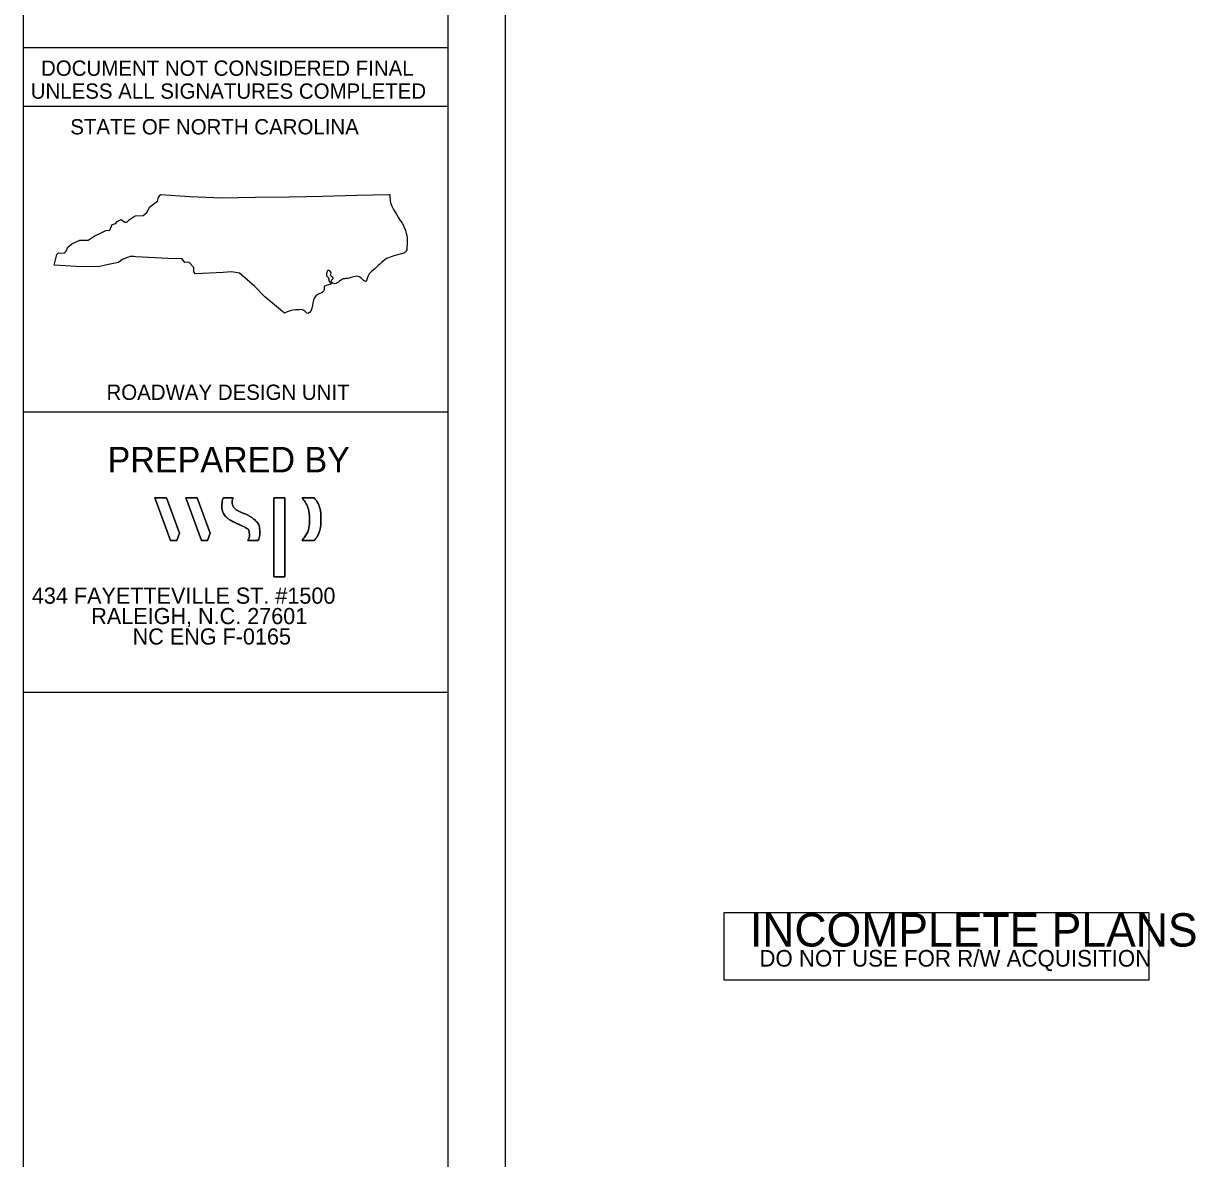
# Model space of a CAD drawing. Extents: x 1553884 to 1554215, y 810431 to 810779.
# Drawn here: x 1554139.32 to 1554180.72, y 810513.45 to 810553.55 of the extents above; entities that cross this region are included whole.
import ezdxf

# ---------------------------------------------------------------- set-up
doc = ezdxf.new("R2010")
doc.units = 0
for name, color, linetype in [('Old_Level_1', 7, 'Continuous'), ('Old_Level_11', 7, 'Continuous'), ('Old_Level_2', 7, 'Continuous'), ('Prop Lane Arrow CELL', 7, 'Continuous'), ('Sheet Professional Seal CELL', 7, 'Continuous'), ('Typical Arrow Superelevation CELL', 7, 'Continuous')]:
    doc.layers.add(name, color=color, linetype=linetype)

msp = doc.modelspace()

# ---------------------------------------------------------------- linework, layer by layer
at = {"layer": 'Old_Level_1'}
msp.add_line((1554152.261, 810547.506), (1554152.26, 810547.512), dxfattribs=at)
for points in [[(1554140.411, 810545.014), (1554140.505, 810545.385), (1554140.563, 810545.452), (1554140.763, 810545.439), (1554140.831, 810545.504), (1554140.884, 810545.649), (1554141.034, 810545.766), (1554141.313, 810545.893), (1554141.607, 810545.896), (1554141.815, 810546.042), (1554142.093, 810546.166), (1554142.232, 810546.24), (1554142.367, 810546.244), (1554142.457, 810546.447), (1554142.59, 810546.485), (1554142.634, 810546.557), (1554142.776, 810546.624), (1554142.905, 810546.528), (1554142.975, 810546.535), (1554143.055, 810546.608), (1554143.264, 810546.759), (1554143.55, 810546.762), (1554143.678, 810546.872), (1554143.789, 810547.076), (1554143.929, 810547.174), (1554144.058, 810547.274), (1554144.086, 810547.41), (1554144.17, 810547.512)], [(1554144.17, 810547.512), (1554145.195, 810547.439), (1554146.328, 810547.395), (1554147.502, 810547.41), (1554148.701, 810547.431), (1554149.88, 810547.451), (1554151.099, 810547.487), (1554152.227, 810547.512), (1554152.26, 810547.512)], [(1554148.542, 810543.318), (1554147.846, 810543.89), (1554147.492, 810544.257), (1554146.948, 810544.727), (1554146.667, 810544.772), (1554146.371, 810544.758), (1554145.397, 810544.71), (1554145.341, 810544.781), (1554145.34, 810544.853), (1554145.336, 810544.925), (1554145.157, 810545.122), (1554145.019, 810545.104), (1554144.923, 810545.238), (1554144.424, 810545.252), (1554143.295, 810545.303), (1554143.224, 810545.316), (1554143.089, 810545.316), (1554142.81, 810545.217), (1554142.675, 810545.111), (1554142.261, 810545.024), (1554141.967, 810544.956), (1554141.18, 810544.966), (1554140.411, 810545.014)]]:
    msp.add_lwpolyline(points, dxfattribs=at)
for points in [[(1554152.261, 810547.506), (1554152.277, 810547.285), (1554152.692, 810546.496), (1554152.842, 810546.146), (1554152.874, 810545.785), (1554152.856, 810545.553)], [(1554152.405, 810545.344), (1554152.149, 810545.242), (1554151.678, 810544.838), (1554151.497, 810544.636), (1554151.406, 810544.431), (1554151.204, 810544.585), (1554150.774, 810544.545), (1554150.618, 810544.524), (1554150.275, 810544.362), (1554150.209, 810544.411), (1554150.206, 810544.477), (1554150.264, 810544.543), (1554150.164, 810544.665), (1554150.189, 810544.73), (1554150.074, 810544.825), (1554150.036, 810544.758), (1554150.037, 810544.619), (1554150.102, 810544.556), (1554150.099, 810544.487), (1554150.185, 810544.351), (1554149.959, 810544.267), (1554149.933, 810544.12), (1554149.724, 810543.979), (1554149.538, 810543.684), (1554149.427, 810543.341), (1554149.36, 810543.308), (1554149.227, 810543.415), (1554149, 810543.432), (1554148.934, 810543.433), (1554148.542, 810543.318)], [(1554152.856, 810545.553), (1554152.822, 810545.479), (1554152.757, 810545.441), (1554152.405, 810545.344)]]:
    msp.add_spline(points, degree=3, dxfattribs=at)
at = {"layer": 'Old_Level_2'}
for p, q in [((1554139.321, 810434.329), (1554139.325, 810592.576)), ((1554154.321, 810434.329), (1554154.325, 810592.576)), ((1554154.325, 810552.688), (1554139.325, 810552.688)), ((1554154.325, 810550.618), (1554139.325, 810550.618)), ((1554154.325, 810539.818), (1554139.325, 810539.818)), ((1554154.325, 810529.918), (1554139.325, 810529.918))]:
    msp.add_line(p, q, dxfattribs=at)
at = {"layer": 'Prop Lane Arrow CELL'}
msp.add_line((1554156.35, 810430.954), (1554156.35, 810595.951), dxfattribs=at)
at = {"layer": 'Sheet Professional Seal CELL'}
msp.add_lwpolyline([(1554164.067, 810519.749), (1554164.067, 810522.147), (1554179.067, 810522.147), (1554179.067, 810519.749)], close=True, dxfattribs=at)
at = {"layer": 'Typical Arrow Superelevation CELL'}
for p, q in [((1554144.52, 810535.284), (1554143.963, 810536.793)), ((1554143.963, 810536.793), (1554144.369, 810536.793)), ((1554144.369, 810536.793), (1554144.83, 810535.542)), ((1554145.607, 810535.284), (1554145.051, 810536.793)), ((1554145.051, 810536.793), (1554145.456, 810536.793)), ((1554145.456, 810536.793), (1554145.918, 810535.542)), ((1554148.166, 810534.005), (1554148.166, 810536.793)), ((1554148.166, 810536.793), (1554148.554, 810536.793)), ((1554148.554, 810536.793), (1554148.554, 810534.005)), ((1554144.83, 810535.542), (1554144.735, 810535.284)), ((1554145.918, 810535.542), (1554145.823, 810535.284)), ((1554144.735, 810535.284), (1554144.52, 810535.284)), ((1554145.823, 810535.284), (1554145.607, 810535.284)), ((1554148.554, 810534.005), (1554148.166, 810534.005))]:
    msp.add_line(p, q, dxfattribs=at)
for points in [[(1554144.369, 810536.793), (1554143.963, 810536.793), (1554144.52, 810535.284), (1554144.735, 810535.284), (1554144.83, 810535.542), (1554144.369, 810536.793)], [(1554145.456, 810536.793), (1554145.051, 810536.793), (1554145.607, 810535.284), (1554145.823, 810535.284), (1554145.918, 810535.542), (1554145.456, 810536.793)], [(1554148.554, 810534.005), (1554148.554, 810536.793), (1554148.166, 810536.793), (1554148.166, 810534.005), (1554148.554, 810534.005)]]:
    msp.add_lwpolyline(points, dxfattribs=at)
for points in [[(1554146.33, 810536.569), (1554146.336, 810536.647), (1554146.35, 810536.723), (1554146.382, 810536.793), (1554146.382, 810536.793), (1554146.737, 810536.793), (1554146.737, 810536.793), (1554146.707, 810536.74), (1554146.679, 810536.642), (1554146.711, 810536.545), (1554146.74, 810536.457), (1554146.8, 810536.398), (1554146.877, 810536.348), (1554146.967, 810536.29), (1554147.073, 810536.258), (1554147.17, 810536.212), (1554147.272, 810536.165), (1554147.371, 810536.115), (1554147.456, 810536.041), (1554147.58, 810535.934), (1554147.655, 810535.807), (1554147.667, 810535.642), (1554147.669, 810535.622), (1554147.67, 810535.602), (1554147.67, 810535.583), (1554147.67, 810535.48), (1554147.653, 810535.377), (1554147.607, 810535.284), (1554147.607, 810535.284), (1554147.243, 810535.284), (1554147.243, 810535.284), (1554147.279, 810535.345), (1554147.307, 810535.428), (1554147.302, 810535.505), (1554147.289, 810535.695), (1554147.057, 810535.799), (1554146.862, 810535.886), (1554146.833, 810535.899), (1554146.804, 810535.912), (1554146.776, 810535.925), (1554146.69, 810535.965), (1554146.606, 810536.011), (1554146.534, 810536.071), (1554146.458, 810536.134), (1554146.401, 810536.196), (1554146.366, 810536.288), (1554146.335, 810536.369), (1554146.324, 810536.456), (1554146.328, 810536.542), (1554146.328, 810536.551), (1554146.329, 810536.56), (1554146.33, 810536.569)], [(1554146.33, 810536.569), (1554146.329, 810536.56), (1554146.328, 810536.551), (1554146.328, 810536.542), (1554146.324, 810536.456), (1554146.335, 810536.369), (1554146.366, 810536.288), (1554146.401, 810536.196), (1554146.458, 810536.134), (1554146.534, 810536.071), (1554146.606, 810536.011), (1554146.69, 810535.965), (1554146.776, 810535.925), (1554146.804, 810535.912), (1554146.833, 810535.899), (1554146.862, 810535.886), (1554147.057, 810535.799), (1554147.289, 810535.695), (1554147.302, 810535.505), (1554147.307, 810535.428), (1554147.279, 810535.345), (1554147.243, 810535.284), (1554147.243, 810535.284), (1554147.607, 810535.284), (1554147.607, 810535.284), (1554147.653, 810535.377), (1554147.67, 810535.48), (1554147.67, 810535.583), (1554147.67, 810535.602), (1554147.669, 810535.622), (1554147.667, 810535.642), (1554147.655, 810535.807), (1554147.58, 810535.934), (1554147.456, 810536.041), (1554147.371, 810536.115), (1554147.272, 810536.165), (1554147.17, 810536.212), (1554147.073, 810536.258), (1554146.967, 810536.29), (1554146.877, 810536.348), (1554146.8, 810536.398), (1554146.74, 810536.457), (1554146.711, 810536.545), (1554146.679, 810536.642), (1554146.707, 810536.74), (1554146.737, 810536.793), (1554146.737, 810536.793), (1554146.382, 810536.793), (1554146.382, 810536.793), (1554146.35, 810536.723), (1554146.336, 810536.647), (1554146.33, 810536.569)], [(1554149.421, 810536.04), (1554149.421, 810536.356), (1554149.306, 810536.62), (1554149.154, 810536.793), (1554149.154, 810536.793), (1554149.594, 810536.793), (1554149.594, 810536.793), (1554149.738, 810536.617), (1554149.828, 810536.318), (1554149.828, 810536.04), (1554149.828, 810536.04), (1554149.828, 810536.039), (1554149.828, 810536.039), (1554149.828, 810535.76), (1554149.738, 810535.46), (1554149.593, 810535.284), (1554149.593, 810535.284), (1554149.153, 810535.284), (1554149.153, 810535.284), (1554149.305, 810535.457), (1554149.421, 810535.722), (1554149.421, 810536.039), (1554149.421, 810536.039), (1554149.421, 810536.04), (1554149.421, 810536.04)], [(1554149.421, 810536.04), (1554149.421, 810536.04), (1554149.421, 810536.039), (1554149.421, 810536.039), (1554149.421, 810535.722), (1554149.305, 810535.457), (1554149.153, 810535.284), (1554149.153, 810535.284), (1554149.593, 810535.284), (1554149.593, 810535.284), (1554149.738, 810535.46), (1554149.828, 810535.76), (1554149.828, 810536.039), (1554149.828, 810536.039), (1554149.828, 810536.04), (1554149.828, 810536.04), (1554149.828, 810536.318), (1554149.738, 810536.617), (1554149.594, 810536.793), (1554149.594, 810536.793), (1554149.154, 810536.793), (1554149.154, 810536.793), (1554149.306, 810536.62), (1554149.421, 810536.356), (1554149.421, 810536.04)]]:
    msp.add_open_spline(points, degree=3, dxfattribs=at)

# ---------------------------------------------------------------- texts
at = {"layer": 'Old_Level_11'}
for s, p in [('434 FAYETTEVILLE ST. #1500', (1554139.619, 810533.053)), ('RALEIGH, N.C. 27601', (1554141.717, 810532.332)), ('NC ENG F-0165', (1554143.177, 810531.611))]:
    msp.add_text(s, height=0.57009, rotation=360, dxfattribs=at).set_placement(p)
at = {"layer": 'Sheet Professional Seal CELL'}
for s, height, p in [('INCOMPLETE PLANS', 1.17549, (1554164.98, 810520.943)), ('DO NOT USE FOR R/W ACQUISITION', 0.58775, (1554165.312, 810520.233))]:
    msp.add_text(s, height=height, dxfattribs=at).set_placement(p)
at = {"layer": 'Typical Arrow Superelevation CELL'}
for s, height, p in [('DOCUMENT NOT CONSIDERED FINAL', 0.54, (1554139.942, 810551.702)), ('UNLESS ALL SIGNATURES COMPLETED', 0.54, (1554139.578, 810550.892)), ('STATE OF NORTH CAROLINA', 0.54, (1554140.975, 810549.631)), ('ROADWAY DESIGN UNIT', 0.54, (1554142.255, 810540.253)), ('PREPARED BY', 0.9, (1554142.292, 810537.694))]:
    msp.add_text(s, height=height, dxfattribs=at).set_placement(p)

doc.saveas('drawing.dxf')
